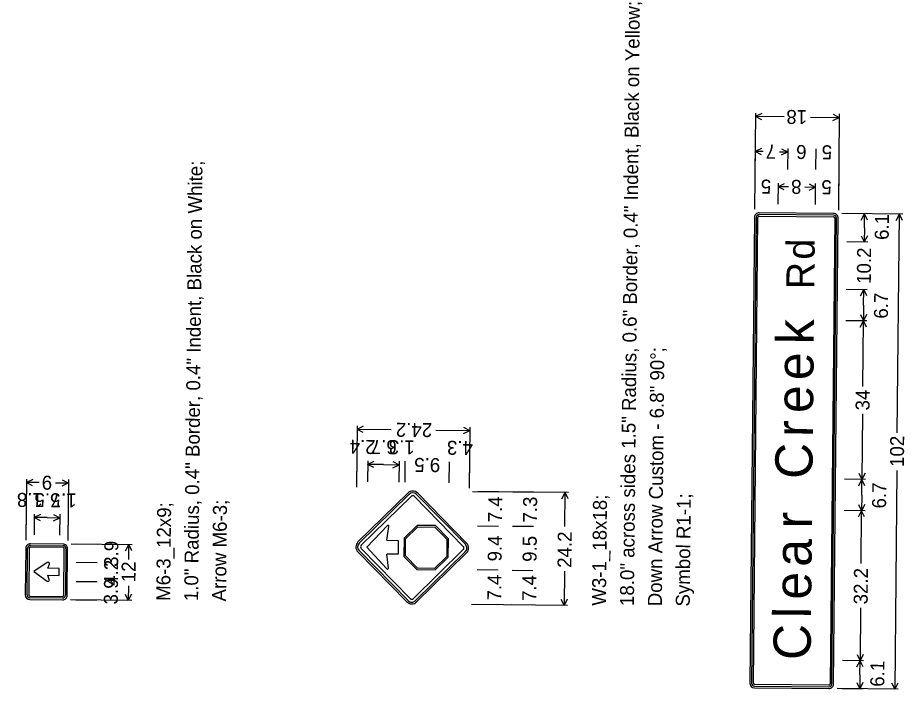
# Model space of a CAD drawing. Extents: x 630289 to 635200, y 364312 to 380651.
# Drawn here: x 631310 to 632272, y 367194 to 367922 of the extents above; entities that cross this region are included whole.
import ezdxf

# ---------------------------------------------------------------- set-up
doc = ezdxf.new("R2010")
doc.units = 0
doc.layers.add('S_CAL_CORNER_ANNOT', color=7, linetype='Continuous')

msp = doc.modelspace()

# ---------------------------------------------------------------- linework, layer by layer
at = {"layer": 'S_CAL_CORNER_ANNOT'}
for p, q in [((632110.28, 367818.67), (632109.24, 367714.46)), ((632117.05, 367818.21), (632110.24, 367814.88)), ((632194.45, 367817.44), (632201.19, 367813.98)), ((632201.23, 367817.77), (632200.19, 367713.55)), ((632141.37, 367814.58), (632110.24, 367814.88)), ((632116.99, 367811.43), (632110.24, 367814.88)), ((632170.06, 367814.29), (632201.19, 367813.98)), ((632194.38, 367810.66), (632201.19, 367813.98)), ((632109.9, 367780.78), (632109.68, 367758.04)), ((632116.68, 367780.31), (632109.86, 367776.99)), ((632138.49, 367780.09), (632145.23, 367776.64)), ((632145.27, 367780.43), (632145.05, 367757.69)), ((632175.59, 367780.12), (632175.36, 367757.39)), ((632175.59, 367780.12), (632175.36, 367757.39)), ((632200.85, 367779.87), (632200.63, 367757.14)), ((632118.64, 367776.9), (632109.86, 367776.99)), ((632116.61, 367773.53), (632109.86, 367776.99)), ((632136.46, 367776.72), (632145.23, 367776.64)), ((632138.42, 367773.31), (632145.23, 367776.64)), ((632109.53, 367742.88), (632109.3, 367720.14)), ((632134.79, 367742.63), (632134.56, 367719.89)), ((632141.56, 367742.16), (632134.75, 367738.84)), ((632168.43, 367741.9), (632175.18, 367738.44)), ((632175.21, 367742.23), (632174.99, 367719.49)), ((632175.21, 367742.23), (632174.99, 367719.49)), ((632200.48, 367741.98), (632200.25, 367719.24)), ((632145.94, 367738.73), (632134.75, 367738.84)), ((632141.5, 367735.38), (632134.75, 367738.84)), ((632163.99, 367738.55), (632175.18, 367738.44)), ((632168.36, 367735.12), (632175.18, 367738.44)), ((632109.15, 367705.62), (632104.13, 367200.33)), ((632195.1, 367709.82), (632114.26, 367710.62)), ((632195.08, 367199.42), (632200.11, 367704.71)), ((632270.27, 367709.07), (632203.95, 367709.73)), ((632232.37, 367709.44), (632209.63, 367709.67)), ((632225.12, 367702.73), (632228.58, 367709.48)), ((632228.43, 367694.18), (632228.58, 367709.48)), ((632231.9, 367702.67), (632228.58, 367709.48)), ((632263.02, 367702.36), (632266.48, 367709.11)), ((632264.12, 367471.75), (632266.48, 367709.11)), ((632269.8, 367702.29), (632266.48, 367709.11)), ((632228.43, 367694.18), (632228.28, 367678.88)), ((632224.95, 367685.69), (632228.28, 367678.88)), ((632231.73, 367685.62), (632228.28, 367678.88)), ((632232.06, 367678.84), (632209.33, 367679.07)), ((632232.06, 367678.84), (632209.33, 367679.07)), ((632231.55, 367627.13), (632208.81, 367627.35)), ((632224.3, 367620.42), (632227.76, 367627.17)), ((632227.59, 367610.24), (632227.76, 367627.17)), ((632231.08, 367620.36), (632227.76, 367627.17)), ((632227.59, 367610.24), (632227.42, 367593.31)), ((632224.1, 367600.13), (632227.42, 367593.31)), ((632230.88, 367600.06), (632227.42, 367593.31)), ((632231.21, 367593.27), (632208.48, 367593.5)), ((632223.97, 367586.57), (632227.42, 367593.31)), ((632226.72, 367522.23), (632227.42, 367593.31)), ((632230.75, 367586.5), (632227.42, 367593.31)), ((632226.42, 367492.34), (632225.71, 367421.26)), ((631677.84, 367479.38), (631677.18, 367413.06)), ((631684.61, 367478.91), (631677.8, 367475.59)), ((631714.75, 367475.22), (631677.8, 367475.59)), ((631684.55, 367472.13), (631677.8, 367475.59)), ((631763.2, 367474.74), (631800.15, 367474.37)), ((631793.34, 367471.05), (631800.15, 367474.37)), ((631793.4, 367477.83), (631800.15, 367474.37)), ((631800.19, 367478.16), (631799.53, 367411.84)), ((631677.46, 367441.48), (631677.23, 367418.74)), ((631689.37, 367441.36), (631689.14, 367418.63)), ((631696.15, 367440.89), (631689.33, 367437.57)), ((631706.39, 367437.4), (631689.33, 367437.57)), ((631696.08, 367434.12), (631689.33, 367437.57)), ((631706.39, 367437.4), (631723.44, 367437.24)), ((631716.63, 367433.91), (631723.44, 367437.24)), ((631716.69, 367440.69), (631723.44, 367437.24)), ((631723.48, 367441.02), (631723.25, 367418.29)), ((631729.79, 367440.96), (631729.57, 367418.22)), ((631777.8, 367440.48), (631777.57, 367417.75)), ((631777.8, 367440.48), (631777.57, 367417.75)), ((631799.81, 367440.27), (631799.59, 367417.53)), ((632222.39, 367428.07), (632225.71, 367421.26)), ((632229.17, 367428), (632225.71, 367421.26)), ((632263.71, 367431.07), (632261.35, 367193.71)), ((631319.02, 367421.77), (631318.36, 367355.45)), ((631325.79, 367421.3), (631318.98, 367417.98)), ((631332.73, 367417.84), (631318.98, 367417.98)), ((631325.72, 367414.52), (631318.98, 367417.98)), ((631350.7, 367417.66), (631364.45, 367417.52)), ((631357.64, 367414.2), (631364.45, 367417.52)), ((631357.71, 367420.98), (631364.45, 367417.52)), ((631364.49, 367421.31), (631363.83, 367354.99)), ((632229.5, 367421.22), (632206.77, 367421.44)), ((632222.26, 367414.51), (632225.71, 367421.26)), ((632225.55, 367404.33), (632225.71, 367421.26)), ((632229.04, 367414.44), (632225.71, 367421.26)), ((631732.93, 367406.49), (631678.81, 367353.43)), ((631796.71, 367352.26), (631743.65, 367406.39)), ((631907.49, 367406.98), (631803.28, 367408.02)), ((631831.7, 367407.73), (631808.97, 367407.96)), ((631869.6, 367407.36), (631846.86, 367407.58)), ((631900.25, 367400.27), (631903.7, 367407.02)), ((631903.34, 367370.07), (631903.7, 367407.02)), ((631907.03, 367400.2), (631903.7, 367407.02)), ((632225.55, 367404.33), (632225.38, 367387.4)), ((632222.06, 367394.22), (632225.38, 367387.4)), ((632228.83, 367394.15), (632225.38, 367387.4)), ((632229.17, 367387.36), (632206.43, 367387.59)), ((632221.92, 367380.65), (632225.38, 367387.4)), ((632224.81, 367330.12), (632225.38, 367387.4)), ((632228.7, 367380.59), (632225.38, 367387.4)), ((631318.64, 367383.87), (631318.41, 367361.13)), ((631327.48, 367383.78), (631327.25, 367361.04)), ((631334.26, 367383.31), (631327.44, 367379.99)), ((631341.34, 367379.85), (631327.44, 367379.99)), ((631334.19, 367376.53), (631327.44, 367379.99)), ((631341.34, 367379.85), (631355.23, 367379.71)), ((631348.42, 367376.39), (631355.23, 367379.71)), ((631348.49, 367383.17), (631355.23, 367379.71)), ((631355.27, 367383.5), (631355.05, 367360.77)), ((631355.27, 367383.5), (631355.05, 367360.77)), ((631364.11, 367383.42), (631363.89, 367360.68)), ((631743.16, 367371.44), (631728.96, 367357.52)), ((631763.05, 367371.24), (631743.16, 367371.44)), ((631776.97, 367357.04), (631763.05, 367371.24)), ((631831.33, 367370.24), (631808.59, 367370.47)), ((631831.33, 367370.24), (631808.59, 367370.47)), ((631869.23, 367370.18), (631846.49, 367370.41)), ((631869.23, 367370.18), (631846.49, 367370.41)), ((631728.96, 367357.52), (631728.77, 367337.63)), ((631776.77, 367337.15), (631776.97, 367357.04)), ((631433.9, 367350.51), (631367.58, 367351.17)), ((631396.01, 367350.88), (631373.27, 367351.11)), ((631426.66, 367343.8), (631430.11, 367350.55)), ((631429.95, 367334.49), (631430.11, 367350.55)), ((631433.44, 367343.73), (631430.11, 367350.55)), ((631678.7, 367342.71), (631731.76, 367288.59)), ((631728.77, 367337.63), (631742.68, 367323.43)), ((631742.48, 367288.48), (631796.61, 367341.54)), ((631762.57, 367323.24), (631776.77, 367337.15)), ((631341.53, 367331.25), (631326.86, 367321.25)), ((631342.36, 367324.89), (631343.92, 367329.43)), ((631395.81, 367330.99), (631373.07, 367331.22)), ((631395.81, 367330.99), (631373.07, 367331.22)), ((631326.86, 367321.25), (631341.33, 367310.97)), ((631342.29, 367317.31), (631354.61, 367317.19)), ((631343.75, 367312.74), (631342.29, 367317.31)), ((631354.69, 367324.76), (631342.36, 367324.89)), ((631354.61, 367317.19), (631354.69, 367324.76)), ((631742.68, 367323.43), (631762.57, 367323.24)), ((631830.86, 367322.88), (631808.12, 367323.1)), ((631868.75, 367322.18), (631846.01, 367322.41)), ((631902.86, 367321.61), (631902.49, 367284.67)), ((631395.6, 367310.14), (631372.86, 367310.37)), ((631429.67, 367305.96), (631429.51, 367289.91)), ((631433.3, 367289.87), (631366.98, 367290.53)), ((631395.4, 367290.25), (631372.67, 367290.48)), ((631426.19, 367296.73), (631429.51, 367289.91)), ((631432.97, 367296.66), (631429.51, 367289.91)), ((631899.17, 367291.48), (631902.49, 367284.67)), ((631905.95, 367291.41), (631902.49, 367284.67)), ((631906.28, 367284.63), (631802.06, 367285.67)), ((631830.48, 367285.38), (631807.75, 367285.61)), ((631868.38, 367285.01), (631845.64, 367285.23)), ((632224.33, 367281.98), (632223.76, 367224.69)), ((632220.44, 367231.5), (632223.76, 367224.69)), ((632227.22, 367231.44), (632223.76, 367224.69)), ((632227.55, 367224.66), (632204.81, 367224.88)), ((632220.3, 367217.95), (632223.76, 367224.69)), ((632223.61, 367209.39), (632223.76, 367224.69)), ((632227.08, 367217.88), (632223.76, 367224.69)), ((632223.61, 367209.39), (632223.46, 367194.09)), ((632109.13, 367195.22), (632189.98, 367194.42)), ((632265.14, 367193.67), (632198.82, 367194.33)), ((632227.24, 367194.05), (632204.51, 367194.28)), ((632220.13, 367200.9), (632223.46, 367194.09)), ((632226.91, 367200.84), (632223.46, 367194.09)), ((632258.03, 367200.53), (632261.35, 367193.71)), ((632264.81, 367200.46), (632261.35, 367193.71))]:
    msp.add_line(p, q, dxfattribs=at)
for points in [[(632111.05, 367705.6), (632106.03, 367200.31)], [(632107.92, 367200.29), (632112.94, 367705.58)], [(632111.05, 367705.6), (632111.05, 367705.6), (632111.05, 367705.6)], [(632114.22, 367706.83), (632195.07, 367706.03)], [(632195.09, 367707.92), (632114.24, 367708.72)], [(632196.32, 367704.75), (632191.29, 367199.46)], [(632193.19, 367199.44), (632198.21, 367704.73)], [(632195.09, 367707.92), (632195.09, 367707.92), (632195.09, 367707.92)], [(631734.26, 367405.14), (631680.13, 367352.08)], [(631734.26, 367405.14), (631734.26, 367405.14), (631734.26, 367405.14)], [(631795.36, 367350.93), (631742.3, 367405.06)], [(631682.35, 367349.83), (631736.47, 367402.88)], [(631740.05, 367402.85), (631793.11, 367348.72)], [(631710.73, 367371.15), (631688.44, 367347.98), (631688.44, 367347.98), (631688.44, 367347.98)], [(631710.31, 367355.34), (631712.34, 367370.36)], [(631743.16, 367371.44), (631728.96, 367357.52)], [(631730.54, 367356.85), (631743.8, 367369.85)], [(631743.16, 367371.44), (631743.16, 367371.44), (631743.16, 367371.44)], [(631763.05, 367371.24), (631743.16, 367371.44)], [(631743.8, 367369.85), (631762.38, 367369.66)], [(631762.38, 367369.66), (631775.38, 367356.4)], [(631776.97, 367357.04), (631763.05, 367371.24)], [(631763.05, 367371.24), (631763.05, 367371.24), (631763.05, 367371.24)], [(631728.96, 367357.52), (631728.77, 367337.63)], [(631728.96, 367357.52), (631728.96, 367357.52), (631728.96, 367357.52)], [(631730.35, 367338.27), (631730.54, 367356.85)], [(631775.38, 367356.4), (631775.19, 367337.83)], [(631776.77, 367337.15), (631776.97, 367357.04)], [(631776.97, 367357.04), (631776.97, 367357.04), (631776.97, 367357.04)], [(631318.27, 367346.6), (631317.77, 367296.07)], [(631319.66, 367296.06), (631320.16, 367346.58)], [(631322.06, 367346.57), (631321.56, 367296.04)], [(631322.06, 367346.57), (631322.06, 367346.57), (631322.06, 367346.57)], [(631358.7, 367347.47), (631323.33, 367347.82)], [(631323.35, 367349.71), (631358.72, 367349.36)], [(631358.74, 367351.25), (631323.37, 367351.61)], [(631358.7, 367347.47), (631358.7, 367347.47), (631358.7, 367347.47)], [(631359.45, 367295.66), (631359.95, 367346.19)], [(631361.85, 367346.17), (631361.35, 367295.64)], [(631363.24, 367295.62), (631363.74, 367346.15)], [(631735.37, 367292.12), (631682.31, 367346.25)], [(631688.44, 367347.98), (631710.27, 367324.37)], [(631722.62, 367355.22), (631722.47, 367340.06), (631710.15, 367340.18)], [(631710.31, 367355.34), (631722.62, 367355.22), (631722.62, 367355.22), (631722.62, 367355.22)], [(631795.36, 367350.93), (631795.36, 367350.93), (631795.36, 367350.93)], [(631680.05, 367344.04), (631733.12, 367289.91)], [(631680.05, 367344.04), (631680.05, 367344.04), (631680.05, 367344.04)], [(631711.89, 367325.12), (631710.15, 367340.18)], [(631728.77, 367337.63), (631742.68, 367323.43)], [(631728.77, 367337.63), (631728.77, 367337.63), (631728.77, 367337.63)], [(631743.36, 367325.01), (631730.35, 367338.27)], [(631793.07, 367345.15), (631738.95, 367292.09)], [(631741.15, 367289.83), (631795.28, 367342.9)], [(631775.19, 367337.83), (631761.93, 367324.82)], [(631762.57, 367323.24), (631776.77, 367337.15)], [(631776.77, 367337.15), (631776.77, 367337.15), (631776.77, 367337.15)], [(631742.68, 367323.43), (631762.57, 367323.24)], [(631742.68, 367323.43), (631742.68, 367323.43), (631742.68, 367323.43)], [(631761.93, 367324.82), (631743.36, 367325.01)], [(631762.57, 367323.24), (631762.57, 367323.24), (631762.57, 367323.24)], [(631322.77, 367290.97), (631358.14, 367290.62)], [(631358.16, 367292.51), (631322.79, 367292.87)], [(631322.81, 367294.76), (631358.18, 367294.41)], [(631322.81, 367294.76), (631322.81, 367294.76), (631322.81, 367294.76)], [(631359.45, 367295.66), (631359.45, 367295.66), (631359.45, 367295.66)], [(631363.24, 367295.62), (631363.24, 367295.62), (631363.24, 367295.62)], [(631741.15, 367289.83), (631741.15, 367289.83), (631741.15, 367289.83)], [(632109.15, 367197.12), (632190, 367196.32)], [(632109.15, 367197.12), (632109.15, 367197.12), (632109.15, 367197.12)], [(632190.02, 367198.21), (632109.17, 367199.01)], [(632193.19, 367199.44), (632193.19, 367199.44), (632193.19, 367199.44)]]:
    msp.add_lwpolyline(points, dxfattribs=at)
for centre, radius, start, end in [((632114.21, 367705.57), 5.05, 89.43036, 179.43057), ((632114.21, 367705.57), 3.16, 89.43036, 179.43057), ((632114.21, 367705.57), 1.26, 89.43036, 179.43057), ((632195.05, 367704.76), 1.26, 359.43042, 89.43063), ((632195.05, 367704.76), 3.16, 359.43042, 89.43063), ((632195.05, 367704.76), 5.05, 359.43042, 89.43063), ((631738.24, 367401.08), 7.58, 44.43052, 134.43016), ((631738.24, 367401.08), 5.68, 44.43052, 134.43016), ((631738.24, 367401.08), 2.53, 44.43052, 134.43016), ((631711.41, 367370.49), 0.945, 352.27761, 135.64598), ((631323.32, 367346.55), 5.05, 89.43036, 179.43057), ((631323.32, 367346.55), 3.16, 89.43036, 179.43057), ((631323.32, 367346.55), 1.26, 89.43036, 179.43057), ((631358.69, 367346.2), 1.26, 359.43042, 89.43063), ((631358.69, 367346.2), 3.16, 359.43042, 89.43063), ((631358.69, 367346.2), 5.05, 359.43042, 89.43063), ((631684.11, 367348.02), 7.58, 134.43035, 224.4301), ((631684.11, 367348.02), 5.68, 134.43035, 224.4301), ((631684.11, 367348.02), 2.53, 134.43035, 224.4301), ((631791.3, 367346.95), 2.53, 314.43031, 44.43052), ((631791.3, 367346.95), 5.68, 314.43031, 44.43052), ((631791.3, 367346.95), 7.58, 314.43031, 44.43052), ((631342.42, 367329.94), 1.58, 341.1015, 124.26188), ((631710.95, 367325.01), 0.945, 223.21486, 6.58322), ((631342.25, 367312.25), 1.58, 234.59896, 17.75876), ((631322.82, 367296.02), 5.05, 179.43057, 269.43021), ((631322.82, 367296.02), 3.16, 179.43057, 269.43021), ((631322.82, 367296.02), 1.26, 179.43057, 269.43021), ((631358.19, 367295.67), 5.05, 269.43021, 359.43042), ((631358.19, 367295.67), 3.16, 269.43021, 359.43042), ((631358.19, 367295.67), 1.26, 269.43021, 359.43042), ((631737.17, 367293.89), 7.58, 224.4301, 314.43031), ((631737.17, 367293.89), 5.68, 224.4301, 314.43031), ((631737.17, 367293.89), 2.53, 224.4301, 314.43031), ((632109.18, 367200.28), 5.05, 179.43057, 269.43021), ((632109.18, 367200.28), 3.16, 179.43057, 269.43021), ((632109.18, 367200.28), 1.26, 179.43057, 269.43021), ((632190.03, 367199.47), 5.05, 269.43021, 359.43042), ((632190.03, 367199.47), 3.16, 269.43021, 359.43042), ((632190.03, 367199.47), 1.26, 269.43021, 359.43042)]:
    msp.add_arc(centre, radius, start, end, dxfattribs=at)

# ---------------------------------------------------------------- texts
for s, height, rotation, p in [('18.0" across sides 1.5" Radius, 0.6" Border, 0.4" Indent, Black on Yellow; ', 15.1594, 89.43036, (631978.28, 367283.91)), ('18', 15.159, 179.43057, (632166.35, 367821.91)), ('7', 15.16, 179.43057, (632132.74, 367784.34)), ('6', 15.16, 179.43057, (632165.79, 367784.01)), ('5', 15.16, 179.43057, (632193.46, 367783.74)), ('1.0" Radius, 0.4" Border, 0.4" Indent, Black on White; ', 15.1594, 89.43036, (631505.3, 367289.16)), ('5', 15.16, 179.43057, (632127.39, 367746.49)), ('8', 15.16, 179.43057, (632160.28, 367746.17)), ('5', 15.16, 179.43057, (632193.08, 367745.84)), ('6.1', 15.159, 89.43036, (632254.83, 367681.1)), ('d', 30.32, 89.43036, (632174.39, 367659.7)), ('10.2', 15.159, 89.43036, (632235.4, 367633.35)), ('R', 30.32, 89.43036, (632174.07, 367627.7)), ('6.7', 15.159, 89.43036, (632253.98, 367595.65)), ('k', 40.43, 89.43036, (632173.48, 367567.82)), ('Down Arrow Custom - 6.8" 90°; ', 15.1594, 89.43036, (632008.6, 367283.61)), ('e', 40.43, 89.43036, (632173.09, 367528.85)), ('e', 40.43, 89.43036, (632172.74, 367493.18)), ('34', 15.159, 89.43036, (632234.04, 367496.06)), ('24.2', 15.159, 179.43057, (631759.49, 367482.36)), ('r', 40.43, 89.43036, (632172.48, 367467.27)), ('2.4', 15.159, 179.43057, (631698.01, 367464.02)), ('6.7', 15.159, 179.43057, (631720.98, 367463.79)), ('1.3', 15.159, 179.43057, (631740.47, 367463.6)), ('4.3', 15.159, 179.43057, (631803.67, 367462.97)), ('102', 15.159, 89.43036, (632271.33, 367434.78)), ('C', 40.43, 89.43036, (632172.03, 367421.79)), ('9.5', 15.159, 179.43057, (631768.16, 367444.37)), ('9', 15.16, 179.43057, (631346.99, 367425.28)), ('6.7', 15.159, 89.43036, (632251.93, 367389.74)), ('1.8', 15.159, 179.43057, (631336.9, 367406.43)), ('5.5', 15.159, 179.43057, (631355.93, 367406.24)), ('1.7', 15.159, 179.43057, (631373.49, 367406.06)), ('Symbol R1-1; ', 15.1594, 89.43036, (632038.92, 367283.31)), ('M6-3_12x9; ', 15.1594, 89.43036, (631474.99, 367289.46)), ('Arrow M6-3; ', 15.1594, 89.43036, (631535.62, 367288.86)), ('7.4', 15.159, 89.43036, (631835.16, 367374.74)), ('7.3', 15.159, 89.43036, (631873.06, 367374.45)), ('W3-1_18x18; ', 15.1594, 89.43036, (631947.96, 367284.22)), ('r', 40.43, 89.43036, (632171.49, 367367.97)), ('9.4', 15.159, 89.43036, (631834.74, 367332.28)), ('9.5', 15.159, 89.43036, (631872.64, 367331.82)), ('24.2', 15.159, 89.43036, (631910.47, 367325.33)), ('a', 40.43, 89.43036, (632171.08, 367326.45)), ('3.9', 15.159, 89.43036, (631418.5, 367326.42)), ('4.2', 15.159, 89.43036, (631418.3, 367305.78)), ('12', 15.159, 89.43036, (631437.29, 367309.68)), ('7.4', 15.159, 89.43036, (631834.32, 367289.89)), ('e', 40.43, 89.43036, (632170.72, 367290.77)), ('32.2', 15.159, 89.43036, (632231.95, 367285.69)), ('3.9', 15.159, 89.43036, (631418.1, 367285.68)), ('7.4', 15.159, 89.43036, (631872.21, 367289.35)), ('l', 40.43, 89.43036, (632170.52, 367270.7)), ('C', 40.43, 89.43036, (632170.07, 367225.23)), ('6.1', 15.159, 89.43036, (632250.01, 367196.31))]:
    msp.add_text(s, height=height, rotation=rotation, dxfattribs=at).set_placement(p)

doc.saveas('drawing.dxf')
